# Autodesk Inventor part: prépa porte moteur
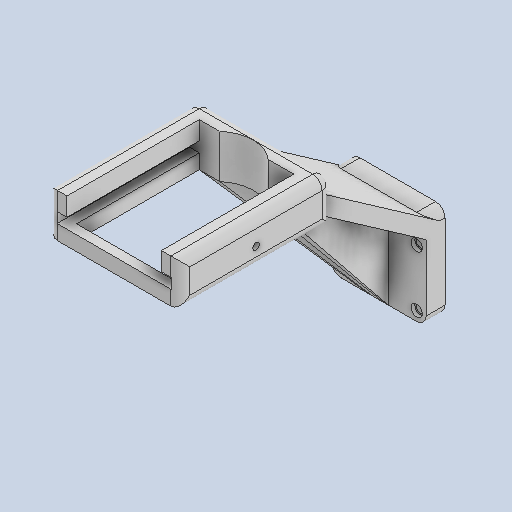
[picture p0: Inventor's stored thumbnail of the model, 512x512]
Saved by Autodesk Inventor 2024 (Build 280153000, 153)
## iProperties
Created: 2026-03
Part Number: prépa porte moteur
Material: Générique
Document SubType Name: Modeling
Designer: bruno
Density: 1 g/cm^3
Appearance: Par défaut
Title: prpa porte moteur.stp
Author: mel
Sending System: Autodesk Inventor 2026
Preprocessor: ST-DEVELOPER v20.1
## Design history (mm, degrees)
feature "Solide1"
node "Solide2"
